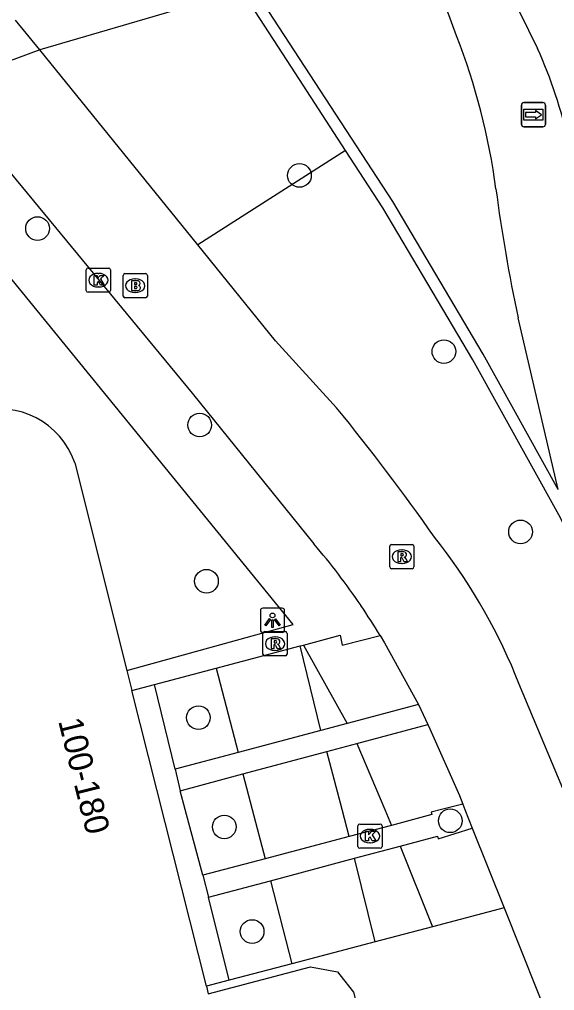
# Model space of a CAD drawing. Extents: x 160806 to 161707, y 383697 to 384148.
# Drawn here: x 161051.44 to 161073.56, y 383742.52 to 383782.67 of the extents above; entities that cross this region are included whole.
import ezdxf

# ---------------------------------------------------------------- set-up
doc = ezdxf.new("R2010")
doc.units = 0
for name, color, linetype in [('IMGEO_Boom', 7, 'Continuous'), ('IMGEO_Brandkraan', 7, 'Continuous'), ('IMGEO_Fietspad_open', 7, 'Continuous'), ('IMGEO_Groenvoorziening', 7, 'Continuous'), ('IMGEO_Kolk', 7, 'Continuous'), ('IMGEO_Lichtpunt', 7, 'Continuous'), ('IMGEO_Muur', 7, 'Continuous'), ('IMGEO_Pand', 7, 'Continuous'), ('IMGEO_Pand_nummerreeks', 7, 'Continuous'), ('IMGEO_Rijbaan_lokaal_gesloten', 7, 'Continuous'), ('IMGEO_Rioolput', 7, 'Continuous'), ('IMGEO_Voetpad_open', 7, 'Continuous'), ('IMGEO_Wegwijzer', 7, 'Continuous')]:
    doc.layers.add(name, color=color, linetype=linetype)

msp = doc.modelspace()

# ---------------------------------------------------------------- linework, layer by layer
at = {"layer": 'IMGEO_Boom'}
for centre in [(161063.016, 383776.218), (161052.192, 383774.021), (161068.987, 383768.934), (161058.891, 383765.899), (161072.153, 383761.48), (161059.174, 383759.44), (161058.84, 383753.8), (161069.249, 383749.537), (161059.91, 383749.283), (161061.06, 383744.957)]:
    msp.add_circle(centre, 0.489, dxfattribs=at)
at = {"layer": 'IMGEO_Brandkraan'}
for p, q in [((161055.729, 383771.233), (161055.729, 383772.085)), ((161055.804, 383772.159), (161056.656, 383772.159)), ((161056.73, 383772.085), (161056.73, 383771.233)), ((161056.217, 383771.939), (161056.242, 383771.939)), ((161056.656, 383771.159), (161055.804, 383771.159)), ((161056.24, 383771.379), (161056.215, 383771.379))]:
    msp.add_line(p, q, dxfattribs=at)
for points in [[(161055.729, 383771.233), (161055.729, 383772.085)], [(161055.804, 383772.159), (161056.656, 383772.159)], [(161056.73, 383772.085), (161056.73, 383771.233)], [(161056.077, 383771.859), (161056.077, 383771.459), (161056.29, 383771.459)], [(161056.308, 383771.859), (161056.077, 383771.859)], [(161056.256, 383771.778), (161056.202, 383771.778), (161056.202, 383771.702)], [(161056.202, 383771.702), (161056.255, 383771.702)], [(161056.264, 383771.626), (161056.202, 383771.626), (161056.202, 383771.545)], [(161056.656, 383771.159), (161055.804, 383771.159)], [(161056.202, 383771.545), (161056.264, 383771.545)]]:
    msp.add_lwpolyline(points, dxfattribs=at)
for centre, radius, start, end in [((161055.806, 383772.083), 0.0765, 91.552, 178.448), ((161055.806, 383772.083), 0.0765, 91.552, 178.448), ((161056.654, 383772.083), 0.0765, 1.552, 88.448), ((161056.654, 383772.083), 0.0765, 1.552, 88.448), ((161056.257, 383771.74), 0.0379, 267.8285, 90.9355), ((161056.265, 383771.585), 0.0404, 269.8759, 90.5077), ((161056.312, 383771.714), 0.145, 59.4692, 91.5367), ((161056.337, 383771.761), 0.0922, 285.5137, 58.1501), ((161056.342, 383771.569), 0.105, 301.3115, 78.989), ((161055.806, 383771.235), 0.0765, 181.552, 268.448), ((161055.806, 383771.235), 0.0765, 181.552, 268.448), ((161056.296, 383771.71), 0.251, 268.6676, 293.5347), ((161056.654, 383771.235), 0.0765, 271.552, 358.448), ((161056.654, 383771.235), 0.0765, 271.552, 358.448)]:
    msp.add_arc(centre, radius, start, end, dxfattribs=at)
for centre, major_axis, ratio, start_param, end_param in [((161056.216, 383771.659), (-0.387, 0.002), 0.722429, 4.712389, 7.853982), ((161056.241, 383771.659), (-0.39, 0.002), 0.717154, 1.570796, 4.712389)]:
    msp.add_ellipse(centre, major_axis=major_axis, ratio=ratio, start_param=start_param, end_param=end_param, dxfattribs=at)
at = {"layer": 'IMGEO_Fietspad_open'}
for points in [[(161052.286, 383781.408), (161051.286, 383782.642)], [(161052.286, 383781.408), (161048.16, 383779.877)], [(161058.823, 383773.343), (161052.286, 383781.408)], [(161048.827, 383779.023), (161058.581, 383767.212), (161063.615, 383760.981)], [(161064.553, 383766.608), (161062.033, 383769.384), (161058.823, 383773.343)], [(161066.348, 383757.197), (161066.526, 383756.895), (161067.941, 383754.348)], [(161080.705, 383733.661), (161080.57, 383734.119), (161077.712, 383741.17), (161074.242, 383750), (161073.898, 383750.874), (161072.088, 383755.217), (161071.934, 383755.585)], [(161067.941, 383754.348), (161068.322, 383753.516)], [(161068.322, 383753.516), (161068.399, 383753.338), (161069.624, 383750.576), (161069.766, 383750.219)], [(161069.766, 383750.219), (161069.854, 383750), (161070.159, 383749.234)], [(161070.159, 383749.234), (161071.475, 383745.935)], [(161071.475, 383745.935), (161073.529, 383740.786)]]:
    msp.add_lwpolyline(points, dxfattribs=at)
for centre, radius, start, end in [((160988.276, 383704.668), 98.259, 35.17137, 39.0782), ((161050.089, 383746.573), 23.631, 22.4177, 38.4481), ((161042.251, 383742.662), 28.143, 34.0796, 40.6109), ((161042.649, 383742.945), 27.654, 31.0224, 34.058)]:
    msp.add_arc(centre, radius, start, end, dxfattribs=at)
at = {"layer": 'IMGEO_Groenvoorziening'}
msp.add_lwpolyline([(161064.925, 383777.254), (161058.823, 383773.343)], dxfattribs=at)
at = {"layer": 'IMGEO_Kolk'}
for p, q in [((161054.281, 383772.387), (161055.133, 383772.387)), ((161054.206, 383771.461), (161054.206, 383772.313)), ((161054.694, 383772.167), (161054.719, 383772.167)), ((161055.207, 383772.313), (161055.207, 383771.461)), ((161054.717, 383771.607), (161054.692, 383771.607)), ((161055.133, 383771.387), (161054.281, 383771.387)), ((161065.431, 383748.477), (161065.431, 383749.329)), ((161065.506, 383749.403), (161066.358, 383749.403)), ((161065.919, 383749.183), (161065.944, 383749.183)), ((161066.432, 383749.329), (161066.432, 383748.477)), ((161066.358, 383748.403), (161065.506, 383748.403)), ((161065.942, 383748.623), (161065.917, 383748.623))]:
    msp.add_line(p, q, dxfattribs=at)
for points in [[(161054.281, 383772.387), (161055.133, 383772.387)], [(161054.206, 383771.461), (161054.206, 383772.313)], [(161054.527, 383772.087), (161054.65, 383772.087), (161054.65, 383771.936), (161054.78, 383772.087), (161054.944, 383772.087), (161054.798, 383771.936), (161054.951, 383771.687), (161054.799, 383771.687), (161054.714, 383771.851), (161054.65, 383771.784), (161054.65, 383771.687), (161054.527, 383771.687), (161054.527, 383772.087)], [(161055.207, 383772.313), (161055.207, 383771.461)], [(161055.133, 383771.387), (161054.281, 383771.387)], [(161065.431, 383748.477), (161065.431, 383749.329)], [(161065.506, 383749.403), (161066.358, 383749.403)], [(161065.752, 383749.103), (161065.875, 383749.103), (161065.875, 383748.952), (161066.005, 383749.103), (161066.169, 383749.103), (161066.023, 383748.952), (161066.176, 383748.703), (161066.024, 383748.703), (161065.939, 383748.867), (161065.875, 383748.8), (161065.875, 383748.703), (161065.752, 383748.703), (161065.752, 383749.103)], [(161066.432, 383749.329), (161066.432, 383748.477)], [(161066.358, 383748.403), (161065.506, 383748.403)]]:
    msp.add_lwpolyline(points, dxfattribs=at)
for centre, start, end in [((161054.283, 383772.311), 91.552, 178.448), ((161054.283, 383772.311), 91.552, 178.448), ((161055.131, 383772.311), 1.552, 88.448), ((161055.131, 383772.311), 1.552, 88.448), ((161054.283, 383771.463), 181.552, 268.448), ((161054.283, 383771.463), 181.552, 268.448), ((161055.131, 383771.463), 271.552, 358.448), ((161055.131, 383771.463), 271.552, 358.448), ((161065.508, 383749.327), 91.552, 178.448), ((161065.508, 383749.327), 91.552, 178.448), ((161066.356, 383749.327), 1.552, 88.448), ((161066.356, 383749.327), 1.552, 88.448), ((161065.508, 383748.479), 181.552, 268.448), ((161065.508, 383748.479), 181.552, 268.448), ((161066.356, 383748.479), 271.552, 358.448), ((161066.356, 383748.479), 271.552, 358.448)]:
    msp.add_arc(centre, 0.0765, start, end, dxfattribs=at)
for centre, major_axis, ratio, start_param, end_param in [((161054.693, 383771.887), (-0.387, 0.002), 0.722429, 4.712389, 7.853982), ((161054.718, 383771.887), (-0.39, 0.002), 0.717154, 1.570796, 4.712389), ((161065.918, 383748.903), (-0.387, 0.002), 0.722429, 4.712389, 7.853982), ((161065.943, 383748.903), (-0.39, 0.002), 0.717154, 1.570796, 4.712389)]:
    msp.add_ellipse(centre, major_axis=major_axis, ratio=ratio, start_param=start_param, end_param=end_param, dxfattribs=at)
at = {"layer": 'IMGEO_Lichtpunt'}
for p, q in [((161062.306, 383758.324), (161061.498, 383758.324)), ((161062.306, 383758.324), (161061.498, 383758.324)), ((161061.404, 383758.229), (161061.404, 383757.422)), ((161061.404, 383758.229), (161061.404, 383757.422)), ((161062.4, 383757.422), (161062.4, 383758.229)), ((161062.4, 383757.422), (161062.4, 383758.229)), ((161061.498, 383757.328), (161062.306, 383757.328)), ((161061.498, 383757.328), (161062.306, 383757.328))]:
    msp.add_line(p, q, dxfattribs=at)
for points in [[(161061.778, 383757.893), (161061.817, 383757.865), (161061.629, 383757.603), (161061.591, 383757.63), (161061.778, 383757.893)], [(161061.88, 383757.845), (161061.927, 383757.845), (161061.927, 383757.523), (161061.88, 383757.523), (161061.88, 383757.845)], [(161061.99, 383757.865), (161062.028, 383757.892), (161062.215, 383757.63), (161062.176, 383757.602), (161061.99, 383757.865)]]:
    msp.add_lwpolyline(points, dxfattribs=at)
msp.add_circle((161061.903, 383758.027), 0.0994, dxfattribs=at)
for centre, start, end in [((161061.498, 383758.229), 90, 180), ((161061.498, 383758.229), 90, 180), ((161062.306, 383758.229), 0, 90), ((161062.306, 383758.229), 0, 90), ((161061.498, 383757.422), 180, 270), ((161061.498, 383757.422), 180, 270), ((161062.306, 383757.422), 270, 0), ((161062.306, 383757.422), 270, 360)]:
    msp.add_arc(centre, 0.0946, start, end, dxfattribs=at)
at = {"layer": 'IMGEO_Muur'}
for points in [[(161073.707, 383763.229), (161070.603, 383768.827), (161066.874, 383775.139), (161061.104, 383784.003)], [(161064.925, 383777.254), (161062.692, 383780.695), (161060.635, 383783.865)], [(161084.716, 383740.669), (161084.276, 383740.472), (161079.903, 383750), (161075.811, 383758.082), (161073.73, 383762.192), (161070.184, 383768.589), (161066.462, 383774.885), (161064.925, 383777.254)]]:
    msp.add_lwpolyline(points, dxfattribs=at)
at = {"layer": 'IMGEO_Pand'}
for points in [[(161053.727, 383764.339), (161055.888, 383755.75)], [(161055.888, 383755.75), (161056.095, 383754.925)], [(161059.171, 383742.697), (161056.095, 383754.925)], [(161059.171, 383742.697), (161059.25, 383742.384), (161063.468, 383743.494), (161064.59, 383743.287), (161064.687, 383743.165), (161065.253, 383742.454), (161065.949, 383739.682), (161066.169, 383738.805), (161067.048, 383735.305), (161067.092, 383735.131), (161064.962, 383734.596), (161065.144, 383733.866), (161066.033, 383730.332), (161066.303, 383729.257), (161066.183, 383728.924)]]:
    msp.add_lwpolyline(points, dxfattribs=at)
msp.add_arc((161050.637, 383763.298), 3.261, 18.6235, 106.7549, dxfattribs=at)
at = {"layer": 'IMGEO_Rijbaan_lokaal_gesloten'}
msp.add_lwpolyline([(161070.257, 383786.787), (161072.86, 383781.463)], dxfattribs=at)
msp.add_arc((161054.965, 383773.421), 19.619, 12.2378, 24.1977, dxfattribs=at)
at = {"layer": 'IMGEO_Rioolput'}
for p, q in [((161066.745, 383760.033), (161066.745, 383760.885)), ((161066.82, 383760.959), (161067.672, 383760.959)), ((161067.233, 383760.739), (161067.258, 383760.739)), ((161067.746, 383760.885), (161067.746, 383760.033)), ((161067.672, 383759.959), (161066.82, 383759.959)), ((161067.256, 383760.179), (161067.231, 383760.179)), ((161061.508, 383756.431), (161061.508, 383757.283)), ((161061.583, 383757.357), (161062.435, 383757.357)), ((161061.996, 383757.137), (161062.021, 383757.137)), ((161062.509, 383757.283), (161062.509, 383756.431)), ((161062.435, 383756.357), (161061.583, 383756.357)), ((161062.019, 383756.577), (161061.994, 383756.577))]:
    msp.add_line(p, q, dxfattribs=at)
for points in [[(161066.745, 383760.033), (161066.745, 383760.885)], [(161066.82, 383760.959), (161067.672, 383760.959)], [(161067.746, 383760.885), (161067.746, 383760.033)], [(161067.334, 383760.657), (161067.082, 383760.659), (161067.082, 383760.259)], [(161067.082, 383760.259), (161067.206, 383760.259), (161067.206, 383760.421), (161067.217, 383760.421)], [(161067.26, 383760.578), (161067.206, 383760.578), (161067.206, 383760.497)], [(161067.206, 383760.497), (161067.258, 383760.497)], [(161067.264, 383760.392), (161067.335, 383760.259), (161067.475, 383760.259), (161067.41, 383760.385)], [(161067.672, 383759.959), (161066.82, 383759.959)], [(161061.508, 383756.431), (161061.508, 383757.283)], [(161061.583, 383757.357), (161062.435, 383757.357)], [(161062.509, 383757.283), (161062.509, 383756.431)], [(161062.097, 383757.055), (161061.845, 383757.057), (161061.845, 383756.657)], [(161061.845, 383756.657), (161061.969, 383756.657), (161061.969, 383756.819), (161061.98, 383756.819)], [(161062.023, 383756.976), (161061.969, 383756.976), (161061.969, 383756.895)], [(161061.969, 383756.895), (161062.021, 383756.895)], [(161062.027, 383756.79), (161062.098, 383756.657), (161062.238, 383756.657), (161062.173, 383756.783)], [(161062.435, 383756.357), (161061.583, 383756.357)]]:
    msp.add_lwpolyline(points, dxfattribs=at)
for centre, radius, start, end in [((161066.822, 383760.883), 0.0765, 91.552, 178.448), ((161066.822, 383760.883), 0.0765, 91.552, 178.448), ((161067.67, 383760.883), 0.0765, 1.552, 88.448), ((161067.67, 383760.883), 0.0765, 1.552, 88.448), ((161067.216, 383760.368), 0.0533, 26.0293, 88.6989), ((161067.242, 383760.686), 0.19, 274.7715, 282.9687), ((161067.266, 383760.482), 0.0964, 77.0061, 93.1865), ((161067.28, 383760.539), 0.0378, 276.6634, 79.6772), ((161067.333, 383760.547), 0.109, 350.3612, 89.416), ((161067.331, 383760.547), 0.112, 277.5842, 350.9817), ((161067.315, 383760.332), 0.108, 29.5134, 73.7905), ((161066.822, 383760.035), 0.0765, 181.552, 268.448), ((161066.822, 383760.035), 0.0765, 181.552, 268.448), ((161067.67, 383760.035), 0.0765, 271.552, 358.448), ((161067.67, 383760.035), 0.0765, 271.552, 358.448), ((161061.585, 383757.281), 0.0765, 91.552, 178.448), ((161061.585, 383757.281), 0.0765, 91.552, 178.448), ((161062.433, 383757.281), 0.0765, 1.552, 88.448), ((161062.433, 383757.281), 0.0765, 1.552, 88.448), ((161061.979, 383756.766), 0.0533, 26.0293, 88.6989), ((161062.005, 383757.084), 0.19, 274.7715, 282.9687), ((161062.029, 383756.88), 0.0964, 77.0061, 93.1865), ((161062.043, 383756.937), 0.0378, 276.6634, 79.6772), ((161062.096, 383756.945), 0.109, 350.3612, 89.416), ((161062.094, 383756.945), 0.112, 277.5842, 350.9817), ((161062.078, 383756.73), 0.108, 29.5134, 73.7905), ((161061.585, 383756.433), 0.0765, 181.552, 268.448), ((161061.585, 383756.433), 0.0765, 181.552, 268.448), ((161062.433, 383756.433), 0.0765, 271.552, 358.448), ((161062.433, 383756.433), 0.0765, 271.552, 358.448)]:
    msp.add_arc(centre, radius, start, end, dxfattribs=at)
for centre, major_axis, ratio, start_param, end_param in [((161067.232, 383760.459), (-0.387, 0.002), 0.722429, 4.712389, 7.853982), ((161067.257, 383760.459), (-0.39, 0.002), 0.717154, 1.570796, 4.712389), ((161061.995, 383756.857), (-0.387, 0.002), 0.722429, 4.712389, 7.853982), ((161062.02, 383756.857), (-0.39, 0.002), 0.717154, 1.570796, 4.712389)]:
    msp.add_ellipse(centre, major_axis=major_axis, ratio=ratio, start_param=start_param, end_param=end_param, dxfattribs=at)
at = {"layer": 'IMGEO_Voetpad_open'}
for points in [[(161069.508, 383781.989), (161068.01, 383786.104)], [(161060.635, 383783.865), (161052.286, 383781.408)], [(161055.888, 383755.75), (161062.76, 383757.656), (161048.332, 383775.339), (161047.132, 383776.763)], [(161073.707, 383763.229), (161072.059, 383770.328)], [(161063.185, 383756.803), (161064.704, 383757.206), (161064.776, 383756.791), (161066.348, 383757.197)], [(161059.57, 383755.846), (161063.041, 383756.765)], [(161063.041, 383756.765), (161063.185, 383756.803)], [(161063.906, 383753.273), (161063.041, 383756.765)], [(161063.185, 383756.803), (161064.984, 383753.56)], [(161057.032, 383755.173), (161059.57, 383755.846)], [(161059.57, 383755.846), (161060.481, 383752.361)], [(161056.095, 383754.925), (161057.032, 383755.173)], [(161057.874, 383751.666), (161057.032, 383755.173)], [(161067.941, 383754.348), (161064.984, 383753.56)], [(161064.984, 383753.56), (161063.906, 383753.273)], [(161065.39, 383752.732), (161068.322, 383753.516)], [(161063.906, 383753.273), (161060.481, 383752.361)], [(161064.141, 383752.398), (161065.39, 383752.732)], [(161065.39, 383752.732), (161066.544, 383750), (161066.819, 383749.348)], [(161060.481, 383752.361), (161057.874, 383751.666)], [(161060.68, 383751.472), (161064.141, 383752.398)], [(161065.072, 383748.886), (161064.777, 383750), (161064.141, 383752.398)], [(161057.874, 383751.666), (161058.084, 383750.778)], [(161058.084, 383750.778), (161060.68, 383751.472)], [(161060.68, 383751.472), (161061.064, 383750), (161061.594, 383747.966)], [(161059.022, 383747.286), (161058.293, 383750), (161058.084, 383750.778)], [(161069.766, 383750.219), (161068.881, 383750), (161068.46, 383749.896), (161068.489, 383749.79), (161066.819, 383749.348)], [(161066.819, 383749.348), (161065.072, 383748.886)], [(161067.183, 383748.487), (161068.725, 383748.898), (161068.752, 383748.795), (161070.159, 383749.234)], [(161065.072, 383748.886), (161061.594, 383747.966)], [(161065.296, 383747.985), (161067.183, 383748.487)], [(161067.183, 383748.487), (161068.513, 383745.156)], [(161061.594, 383747.966), (161059.022, 383747.286)], [(161061.814, 383747.058), (161065.296, 383747.985)], [(161066.149, 383744.533), (161065.296, 383747.985)], [(161059.022, 383747.286), (161059.253, 383746.376)], [(161059.253, 383746.376), (161061.814, 383747.058)], [(161061.814, 383747.058), (161062.701, 383743.626)], [(161060.109, 383742.944), (161059.253, 383746.376)], [(161071.475, 383745.935), (161068.513, 383745.156)], [(161068.513, 383745.156), (161066.149, 383744.533)], [(161066.149, 383744.533), (161062.701, 383743.626)], [(161062.701, 383743.626), (161060.109, 383742.944)], [(161060.109, 383742.944), (161059.171, 383742.697)]]:
    msp.add_lwpolyline(points, dxfattribs=at)
for centre, radius, start, end in [((161043.761, 383771.984), 27.622, 7.645, 21.2353), ((161134.494, 383783.86), 63.885, 187.37512, 192.22857)]:
    msp.add_arc(centre, radius, start, end, dxfattribs=at)
at = {"layer": 'IMGEO_Wegwijzer'}
for p, q in [((161072.291, 383779.229), (161073.081, 383779.229)), ((161073.081, 383779.229), (161072.291, 383779.229)), ((161072.191, 383778.329), (161072.191, 383779.129)), ((161072.191, 383779.129), (161072.191, 383778.329)), ((161073.181, 383779.129), (161073.181, 383778.329)), ((161073.181, 383778.329), (161073.181, 383779.129)), ((161073.081, 383778.229), (161072.291, 383778.229)), ((161072.291, 383778.229), (161073.081, 383778.229))]:
    msp.add_line(p, q, dxfattribs=at)
for points in [[(161072.292, 383778.961), (161073.08, 383778.961), (161073.08, 383778.497), (161072.292, 383778.497), (161072.292, 383778.961)], [(161072.357, 383778.813), (161072.357, 383778.729), (161072.357, 383778.645), (161072.768, 383778.645), (161072.768, 383778.562), (161073.015, 383778.729), (161072.768, 383778.896), (161072.768, 383778.813), (161072.357, 383778.813)]]:
    msp.add_lwpolyline(points, dxfattribs=at)
for centre, start, end in [((161072.291, 383779.129), 90, 180), ((161072.291, 383779.129), 90, 180), ((161073.081, 383779.129), 0, 90), ((161073.081, 383779.129), 360, 90), ((161072.291, 383778.329), 180, 270), ((161072.291, 383778.329), 180, 270), ((161073.081, 383778.329), 270, 0), ((161073.081, 383778.329), 270, 0)]:
    msp.add_arc(centre, 0.1, start, end, dxfattribs=at)

# ---------------------------------------------------------------- texts
at = {"layer": 'IMGEO_Pand_nummerreeks'}
msp.add_text('100-180', height=1, rotation=284.0373, dxfattribs=at).set_placement((161053.04, 383753.666))

doc.saveas('drawing.dxf')
